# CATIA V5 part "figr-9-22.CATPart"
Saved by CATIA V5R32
Part number: Part3
Bounding box of the stored display mesh (mm): x -112 to 0, y -101.683 to 103.294, z -80.304 to 44.415
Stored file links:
  D:\PROJECTS\Project 2022\CATIA V5 6R 2022\Resources\Part Files\c09_catia_v5_6r2022_prt\c09_catia_v5_6r2022_prt\figr-9-22.CATPart
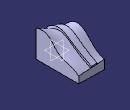
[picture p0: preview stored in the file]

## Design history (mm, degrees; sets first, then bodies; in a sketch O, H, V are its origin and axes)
Set1
  Plane1: type Offset, RefPlane yz-plane, Offset -112
  Plane2: type Offset, RefPlane yz-plane, Offset -63
  Plane3: type Normal, Curve Sketch4, RefPoint vertex of Sketch4
Body1 (main body)
  Sketch1 on yz-plane, origin (0, 0, 0), H (0, 1, 0), V (0, 0, 1)
    spline S1 through (-92.6897, 40.1119) (-30, 30) (10, -10) (60, -30) (97.3103, -50.3041)
    line L1 (97.3103, -50.3041) -> (97.3103, -80.3041)
    line L2 (97.3103, -80.3041) -> (-92.6897, -80.3041)
    line L3 (-92.6897, -80.3041) -> (-92.6897, 40.1119)
    point P3 (-92.6897, 40.1119)
    point P4 (97.3103, -50.3041)
    point P5 (-92.6897, 40.1119)
    point P6 (97.3103, -50.3041)
    vertical: L1 V, L3 V
    horizontal: L2 H
    coincidence: P5 P3, P6 P4
  Sketch2 on Plane1, origin (-112, 0, 0), H (0, 1, 0), V (0, 0, 1)
    spline S1 through (-90, -30) (-70, 10) (-20, 40) (40, 0) (100, -40)
    line L1 (100, -40) -> (100, -80)
    line L2 (100, -80) -> (-90, -80)
    line L3 (-90, -80) -> (-90, -30)
    point P3 (-90, -30)
    point P4 (100, -40)
    point P5 (40, 0)
    point P6 (-90, -30)
    point P7 (100, -40)
    coincidence: P5 H, P6 P3, P7 P4
    vertical: L1 V, L3 V
    horizontal: L2 H
  Loft1: Sections (Sketch1; Sketch2)
  Sketch3 on Plane3, origin (0, -40.1726, -44.9298), H (1, 0, 0), V (0, -0.7455, 0.6665)
    point P1 (-63, 68.4187)
    line L1 (-63, 68.4187) -> (-75.2117, 62.4925)
    line L2 (-75.2117, 62.4925) -> (-79.6266, 71.5898)
    line L3 (-79.6266, 71.5898) -> (-57.1205, 82.5119)
    line L4 (-57.1205, 82.5119) -> (-52.7056, 73.4145)
    point P5 (-52.7056, 73.4145)
    line L5 (-52.7056, 73.4145) -> (-63, 68.4187)
    reference projected point E1 (-63, 68.4187) from vertex of Sketch4
    perpendicularity: L2 L1
    parallelism: L3 L1, L4 L2, L5 L1
    coincidence: P5 L1, P1 E1
  Sketch4 on Plane2, origin (-63, 0, 0), H (0, 1, 0), V (0, 0, 1)
    intersected curve E1 from face of Loft1
  Rib1: profile Sketch3, centre curve Sketch4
